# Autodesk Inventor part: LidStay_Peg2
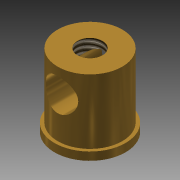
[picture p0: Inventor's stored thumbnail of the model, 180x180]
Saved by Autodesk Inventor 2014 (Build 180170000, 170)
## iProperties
Created: 2014-03
Part Number: LidStay_Peg2
Material: Brass, Soft Yellow
Document SubType Name: Modeling
Designer: Beast
Density: 8.47 g/cm^3
Appearance: Brass - Satin
Author: Beast
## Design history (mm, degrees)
sketch "Sketch1"
  geometry: C1 r 6.985 at (0, 0); 1 further point
  constraints: 1 centre point, 1 coincident
  dimensions: "d0" = 13.97 diameter of C1
extrude "Extrusion1" new body sketch "Sketch1" distance "d1" = 1.5875; taper "d2" = 0 deg
sketch "Sketch2"
  geometry: C1 r 6.985 at (0, 0) reference; C2 r 6.35 at (0, 0)
  constraints: 1 centre point, 1 coincident
  dimensions: "d3" = 12.7 diameter of C2
extrude "Extrusion2" join sketch "Sketch2" distance "d4" = 12.7; taper "d5" = 0 deg
workplane "Work Plane1"
sketch "Sketch3"
  geometry: L1 (-6.985, -1.587)-(6.985, -1.587) reference; 2 further points
  dimensions: "d6" = 9.525 distance from line of L1 point (0, 7.938)
hole "Hole1" sketch "Sketch3" at (0, 7.938) diameter "d7" = 6.35; stored, may be unused: countersink angle "d11" = 82 deg, drill point angle "d13" = 118 deg; dims "d8" = 19.05, "d9" = 9.525, "d10" = 6.35, "d12" = 25.4
sketch "Sketch4"
  geometry: C1 r 6.35 at (0, 0) reference; 1 further point
  constraints: 1 coincident
hole "Hole2" sketch "Sketch4" at (0, 0) diameter "d14" = 4.9276; stored, may be unused: countersink angle "d18" = 82 deg, drill point angle "d20" = 118 deg; dims "d15" = 19.05, "d16" = 9.525, "d17" = 6.35, "d19" = 25.4
body "Solid1"
